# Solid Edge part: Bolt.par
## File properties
Author: Sarvanan
Template: Sync Iso Part.par
Last saved by: Cadcim
Revision: 6
Application: Solid Edge
Accuracy: 0.990
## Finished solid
Body 1: solid body, 12 faces, 22 edges, 12 vertices.
  Faces by surface: plane 7, spun 4, cylinder 1
  Edges by curve: line 8, circle 7, intersection 7
Bounding box of the edges (mm; curved faces can reach further): 24.000 x 24.000 x 104.000, from (0, -2.3071, 0) to (24, 21.6929, 104).
Cylindrical faces by radius (mm): R6 x1
Planar faces by outward normal: +x 1, +y 1, +z 2, -x 1, -y 1, -z 1
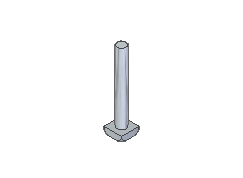
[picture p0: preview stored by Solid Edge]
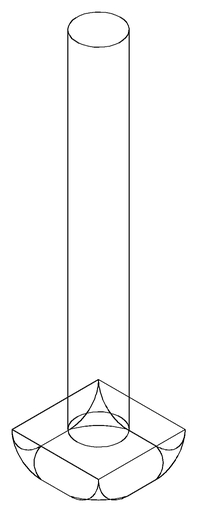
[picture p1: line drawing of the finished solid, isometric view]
